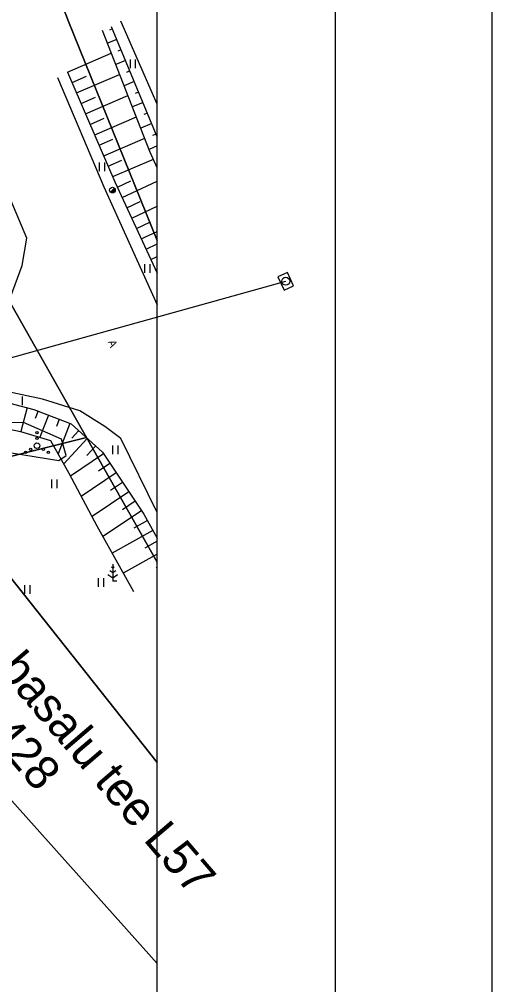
# Model space of a CAD drawing. Extents: x 532656 to 533339, y 6581345 to 6581629.
# Drawn here: x 533297.5 to 533338.9, y 6581463.1 to 6581547.8 of the extents above; entities that cross this region are included whole.
import ezdxf

# ---------------------------------------------------------------- set-up
doc = ezdxf.new("R2010")
doc.units = 0
for name, color, linetype in [('HALJASTUS', 7, 'Continuous'), ('PIIR', 7, 'Continuous'), ('POST', 7, 'Continuous'), ('PR_SIDE', 7, 'Continuous'), ('PUU', 7, 'Continuous'), ('RELJEEF', 7, 'Continuous'), ('TEE', 7, 'Continuous'), ('VORMISTUS', 7, 'Continuous')]:
    doc.layers.add(name, color=color, linetype=linetype)

msp = doc.modelspace()

# ---------------------------------------------------------------- linework, layer by layer
at = {"layer": 'HALJASTUS'}
for p, q in [((533307.211, 6581544.271), (533307.211, 6581543.51)), ((533307.666, 6581544.271), (533307.666, 6581543.51)), ((533304.51, 6581535.234), (533304.51, 6581534.473)), ((533304.966, 6581535.234), (533304.966, 6581534.473)), ((533308.477, 6581526.324), (533308.477, 6581525.563)), ((533308.932, 6581526.324), (533308.932, 6581525.563)), ((533297.739, 6581514.711), (533297.739, 6581513.95)), ((533305.681, 6581510.404), (533305.681, 6581509.643)), ((533306.137, 6581510.404), (533306.137, 6581509.643)), ((533300.322, 6581507.405), (533300.322, 6581506.644)), ((533300.777, 6581507.405), (533300.777, 6581506.644)), ((533304.416, 6581498.749), (533304.416, 6581497.988)), ((533304.871, 6581498.749), (533304.871, 6581497.988)), ((533297.954, 6581498.134), (533297.954, 6581497.373)), ((533298.409, 6581498.134), (533298.409, 6581497.373))]:
    msp.add_line(p, q, dxfattribs=at)
msp.add_lwpolyline([(533301.596, 6581509.531), (533301.205, 6581510.943), (533297.872, 6581512.419), (533293.85, 6581512.397), (533292.416, 6581511.385), (533293.032, 6581509.744), (533296.798, 6581509.751), (533300.946, 6581509.084), (533301.596, 6581509.531)], dxfattribs=at)
for centre, radius in [((533299.042, 6581511.534), 0.1), ((533299.042, 6581510.384), 0.25), ((533299.042, 6581511.034), 0.1), ((533298.042, 6581509.809), 0.1), ((533298.477, 6581510.059), 0.1), ((533299.607, 6581510.059), 0.1), ((533300.042, 6581509.809), 0.1)]:
    msp.add_circle(centre, radius, dxfattribs=at)
at = {"layer": 'PIIR'}
for points in [[(533309.595, 6581500.161), (533303.4, 6581511.09), (533294.3, 6581527.13), (533291.41, 6581534.01), (533261.482, 6581605.423)], [(533271.422, 6581605.423), (533276.24, 6581599.38), (533288.27, 6581583.12), (533301.8, 6581547.63), (533309.595, 6581528.399)], [(533309.595, 6581528.399), (533301.8, 6581547.63), (533288.27, 6581583.12), (533308.1, 6581556.05), (533309.595, 6581552.261)], [(533309.595, 6581482.585), (533289.68, 6581507.68), (533303.4, 6581511.09), (533309.595, 6581500.161)], [(533309.595, 6581464.945), (533292.38, 6581484.15), (533267.77, 6581502.5), (533289.68, 6581507.68), (533309.595, 6581482.585)], [(533141.128, 6581421.679), (533127.07, 6581468.59), (533267.77, 6581502.5), (533292.38, 6581484.15), (533309.595, 6581464.945)]]:
    msp.add_lwpolyline(points, dxfattribs=at)
msp.add_lwpolyline([(533291.41, 6581534.01), (533294.3, 6581527.13), (533303.4, 6581511.09), (533289.68, 6581507.68), (533271.76, 6581529.44)], close=True, dxfattribs=at)
at = {"layer": 'POST'}
msp.add_line((533305.487, 6581532.643), (533305.84, 6581532.997), dxfattribs=at)
msp.add_circle((533305.664, 6581532.82), 0.25, dxfattribs=at)
for radius, start, end in [(0.225, 224.85406, 45.03563), (0.2, 224.84272, 45.04698), (0.175, 224.82813, 45.06157), (0.15, 224.80867, 45.08103), (0.125, 224.78144, 45.10826), (0.1, 224.74058, 45.14911), (0.075, 224.67249, 45.2172), (0.05, 224.53632, 45.35338), (0.025, 224.12776, 45.76193)]:
    msp.add_arc((533305.664, 6581532.82), radius, start, end, dxfattribs=at)
at = {"layer": 'PR_SIDE'}
msp.add_lwpolyline([(533009.759, 6581491.731), (533020.322, 6581490.227), (533026.333, 6581489.107), (533037.708, 6581487.732), (533062.593, 6581483.646), (533088.347, 6581480.21), (533108.952, 6581471.921), (533120.75, 6581471.502), (533130.735, 6581472.15), (533152.719, 6581477.273), (533179.95, 6581485.593), (533320.872, 6581524.815)], dxfattribs=at)
msp.add_lwpolyline([(533321.567, 6581524.419), (533321.023, 6581525.6), (533320.178, 6581525.212), (533320.722, 6581524.031)], close=True, dxfattribs=at)
msp.add_circle((533320.872, 6581524.815), 0.35, dxfattribs=at)
at = {"layer": 'PUU'}
for p, q in [((533305.693, 6581499.236), (533305.427, 6581499.414)), ((533305.693, 6581499.636), (533305.569, 6581499.719)), ((533305.693, 6581499.986), (533305.693, 6581498.486)), ((533305.818, 6581499.719), (533305.693, 6581499.636)), ((533305.96, 6581499.414), (533305.693, 6581499.236)), ((533305.269, 6581499.075), (533305.693, 6581498.792)), ((533305.693, 6581498.792), (533306.117, 6581499.075)), ((533306.053, 6581498.486), (533305.693, 6581498.486))]:
    msp.add_line(p, q, dxfattribs=at)
at = {"layer": 'RELJEEF'}
for p, q in [((533305.664, 6581546.968), (533305.395, 6581546.856)), ((533309.595, 6581537.49), (533305.583, 6581547.162)), ((533306.047, 6581546.044), (533305.223, 6581545.702)), ((533306.43, 6581545.12), (533306.15, 6581545.004)), ((533301.723, 6581543.178), (533305.563, 6581544.838)), ((533306.813, 6581544.197), (533305.955, 6581543.841)), ((533302.12, 6581542.26), (533303.39, 6581542.809)), ((533302.517, 6581541.343), (533306.295, 6581542.976)), ((533307.196, 6581543.273), (533306.905, 6581543.152)), ((533307.579, 6581542.349), (533306.687, 6581541.979)), ((533302.914, 6581540.425), (533304.163, 6581540.965)), ((533303.31, 6581539.507), (533307.028, 6581541.114)), ((533307.963, 6581541.426), (533307.66, 6581541.3)), ((533308.346, 6581540.502), (533307.42, 6581540.118)), ((533304.104, 6581537.671), (533307.761, 6581539.251)), ((533308.729, 6581539.578), (533308.414, 6581539.448)), ((533303.707, 6581538.589), (533304.936, 6581539.12)), ((533309.112, 6581538.654), (533308.152, 6581538.256)), ((533309.495, 6581537.731), (533309.169, 6581537.596)), ((533304.5, 6581536.753), (533305.709, 6581537.275)), ((533304.897, 6581535.835), (533308.493, 6581537.389)), ((533309.595, 6581536.69), (533308.884, 6581536.395)), ((533305.294, 6581534.917), (533306.482, 6581535.431)), ((533305.691, 6581533.999), (533309.257, 6581535.54)), ((533306.099, 6581533.086), (533307.275, 6581533.629)), ((533306.518, 6581532.179), (533309.595, 6581533.6)), ((533306.938, 6581531.271), (533308.106, 6581531.81)), ((533307.357, 6581530.363), (533309.595, 6581531.396)), ((533307.776, 6581529.455), (533308.937, 6581529.991)), ((533308.196, 6581528.547), (533309.595, 6581529.193)), ((533308.615, 6581527.639), (533309.595, 6581528.092)), ((533309.034, 6581526.731), (533309.595, 6581526.99)), ((533309.454, 6581525.824), (533309.595, 6581525.889)), ((533298.181, 6581513.725), (533297.636, 6581511.626)), ((533299.134, 6581513.43), (533298.871, 6581512.758)), ((533300.065, 6581513.065), (533299.305, 6581511.124)), ((533300.996, 6581512.7), (533300.749, 6581512.068)), ((533301.927, 6581512.336), (533300.887, 6581509.679)), ((533302.691, 6581511.701), (533302.086, 6581511.035)), ((533303.431, 6581511.029), (533301.391, 6581508.784)), ((533304.172, 6581510.356), (533303.416, 6581509.525)), ((533304.879, 6581509.656), (533301.985, 6581507.715)), ((533305.436, 6581508.825), (533304.443, 6581508.16)), ((533305.993, 6581507.995), (533302.928, 6581505.94)), ((533306.55, 6581507.164), (533305.5, 6581506.46)), ((533307.107, 6581506.334), (533303.872, 6581504.165)), ((533307.664, 6581505.503), (533306.557, 6581504.761)), ((533308.22, 6581504.672), (533304.833, 6581502.402)), ((533308.733, 6581503.815), (533307.542, 6581503.15)), ((533309.221, 6581502.942), (533305.645, 6581500.945)), ((533309.595, 6581502.005), (533308.516, 6581501.403)), ((533309.595, 6581500.86), (533306.618, 6581499.198)), ((533309.595, 6581499.715), (533309.49, 6581499.656))]:
    msp.add_line(p, q, dxfattribs=at)
for points in [[(533309.595, 6581534.784), (533308.956, 6581536.213), (533304.785, 6581546.815)], [(533301.723, 6581543.178), (533305.883, 6581533.554), (533309.595, 6581525.517)], [(533276.592, 6581511.417), (533282.451, 6581513.098), (533287.357, 6581513.757), (533292.718, 6581514.44), (533295.532, 6581514.413), (533298.77, 6581513.572), (533302.044, 6581512.29), (533304.781, 6581509.803), (533308.425, 6581504.368), (533309.595, 6581502.271)], [(533276.592, 6581511.417), (533282.478, 6581511.983), (533287.494, 6581512.216), (533293.014, 6581512.587), (533297.606, 6581511.635), (533300.228, 6581510.847), (533301.844, 6581507.98), (533304.308, 6581503.346), (533307.513, 6581497.59)]]:
    msp.add_lwpolyline(points, dxfattribs=at)
at = {"layer": 'TEE'}
msp.add_line((533309.595, 6581540.362), (533306.407, 6581547.637), dxfattribs=at)
for points in [[(533300.834, 6581542.715), (533304.915, 6581533.103), (533309.595, 6581522.744)], [(533309.595, 6581504.516), (533306.388, 6581511.03), (533305.005, 6581512.072), (533302.788, 6581513.446), (533299.515, 6581514.457), (533295.949, 6581515.216), (533292.859, 6581515.08), (533287.545, 6581514.499), (533282.671, 6581513.706), (533282.015, 6581518.32), (533286.115, 6581519.072), (533291.163, 6581519.939), (533294.36, 6581521.188), (533296.727, 6581523.417), (533297.752, 6581526.189), (533298.149, 6581528.6), (533294.521, 6581537.152)]]:
    msp.add_lwpolyline(points, dxfattribs=at)
at = {"layer": 'VORMISTUS'}
for points in [[(532967.698, 6581629.013), (533338.948, 6581629.013), (533338.948, 6581366.513), (532967.698, 6581366.513)], [(532981.448, 6581379.013), (532981.448, 6581616.513), (533325.198, 6581616.513), (533325.198, 6581379.013)], [(532981.448, 6581616.513), (533325.198, 6581616.513), (533325.198, 6581379.013), (532981.448, 6581379.013)], [(533309.595, 6581421.679), (533309.595, 6581605.423), (532997.696, 6581605.423), (532997.696, 6581421.679)]]:
    msp.add_lwpolyline(points, close=True, dxfattribs=at)
msp.add_lwpolyline([(533309.595, 6581421.679), (533309.595, 6581605.423)], dxfattribs=at)

# ---------------------------------------------------------------- texts
at = {"layer": 'PIIR'}
for s, p in [('Juuliku-Tabasalu tee L57', (533283.552, 6581504.796)), ('72501:001:1428', (533280.225, 6581501.956))]:
    msp.add_text(s, height=3, rotation=310.48286, dxfattribs=at).set_placement(p)
at = {"layer": 'TEE'}
msp.add_text('A', height=0.7, rotation=292.15834, dxfattribs=at).set_placement((533305.248, 6581519.498))

doc.saveas('drawing.dxf')
